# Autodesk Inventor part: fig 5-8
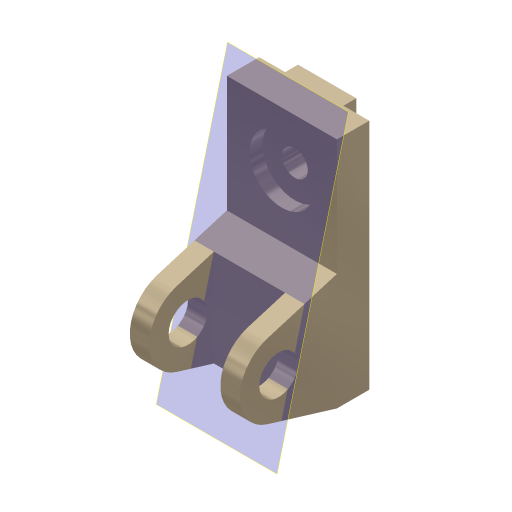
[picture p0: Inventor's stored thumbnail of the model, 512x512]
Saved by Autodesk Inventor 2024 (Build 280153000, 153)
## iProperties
Shininess: 65.0
Angle Display Precision: 2
Document Length Units: 11269
Document Angle Units: 11279
Document Time Units: 11290
Document Mass Units: 11283
Document Length Units Precision: 3
Document Angle Units Precision: 2
Compacted: False
Created: 2001-11
Part Number: fig 5-8
Document SubType Name: Modeling
Designer: Renu Muthoo
Density: 1 g/cm^3
Material: Generic
Appearance: Metal-Titanium (Polished)
Density: 0.0
Volumn: 0.0
Area: 0.0
PropertySet Name: Model Information
Control State: 0
Master: False
Checked Out: False
Author: Renu Muthoo
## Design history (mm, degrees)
sketch "Sketch2"
  geometry: L1 (33.257, 104.664)-(33.257, -75.336); L2 (33.257, -75.336)-(8.257, -75.336); L3 (8.257, -75.336)-(-45.451, -59.045); L4 (-45.451, -1.628)-(8.257, 14.664); L5 (8.257, 14.664)-(8.257, 104.664); L6 (8.257, 104.664)-(33.257, 104.664); C1 r 15 at (-36.743, -30.336); A1 r 30 centre (-36.743, -30.336) between (-45.451, -1.628) and (-45.451, -59.045)
  constraints: 12 end point, 2 centre point, 2 equal length, 2 parallel, 2 point on circle, 2 tangent, 1 coincident, 1 perpendicular, 1 vertical
  dimensions: "d0" = 180 distance of L1.start L1.end; "d1" = 30 radius of A1; "d2" = 25 distance of L5.end L1.start; "d3" = 45 distance from line of L2 A1.centre; "d4" = 70 distance from line of L1 A1.centre; "d5" = 30 diameter of C1
extrude "Extrusion1" new body sketch "Sketch2" distance "d6" = 85; taper "d7" = 0 deg
workplane "Work Plane1"
sketch "Sketch3"
  geometry: L1 (15, 62.364)-(70, 62.364); L2 (70, 62.364)-(70, -52.386); L3 (70, -52.386)-(15, -52.386); L4 (15, -52.386)-(15, 62.364); L5 (0, -45)-(0, -28.708) reference
  constraints: 8 end point, 2 parallel, 1 horizontal, 1 perpendicular
  dimensions: "d8" = 55 distance of L1.start L1.end; "d9" = 15 distance between parallel lines of L5 L4
extrude "Extrusion2" cut sketch "Sketch3" distance "d10" = 50; taper "d11" = 0 deg
sketch "Sketch4"
  geometry: L1 (0, 25)-(85, 25) reference; L2 (0, 0)-(0, 25) reference; L3 (20, 25)-(65, 25); L4 (65, 25)-(65, 35); L5 (65, 35)-(20, 35); L6 (20, 35)-(20, 25)
  constraints: 8 end point, 2 parallel, 1 horizontal, 1 perpendicular, 1 point on line
  dimensions: "d12" = 45 distance of L4.end L5.end; "d13" = 10 distance of L3.end L4.end; "d14" = 20 distance between parallel lines of L2 L6
extrude "Extrusion3" join sketch "Sketch4" stored distance "d15" = 50; taper "d16" = 0 deg
sketch "Sketch5"
  geometry: L1 (85, 0)-(85, 90) reference; L2 (0, 90)-(85, 90) reference; 1 further point
  dimensions: "d17" = 42 distance from line of L2 point (42.5, 48); "d18" = 42.5 distance from line of L1 point (42.5, 48)
hole "Hole1" sketch "Sketch5" diameter "d19" = 20; stored, may be unused: countersink angle "d23" = 82 deg, drill point angle "d25" = 118 deg; dims "d20" = 6, "d21" = 50, "d22" = 10, "d24" = 8
workplane "Work Plane5"
body "Solid1"
node "Sketch1"
